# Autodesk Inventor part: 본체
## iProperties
Created: 2015-01
Part Number: 본체
Material: 알루미늄-6061
Document SubType Name: Modeling
Designer: elite
Mass: 1021.19 g
Surface Area: 1059.8 cm^2
Volume: 376.823 cm^3
Density: 2.71 g/cm^3
Author: elite
